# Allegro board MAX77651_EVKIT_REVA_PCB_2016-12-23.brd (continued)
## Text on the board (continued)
FAB_NOTES: NOTES: | FINISH: | TESTING: | MISCELLANEOUS: | TOOLING: | 15.  CHECK ALL THAT APPLY | 16.  VENDOR LOGO & DATE CODE REQUIRED IN INK ON BOTTOM SIDE ONLY. DATE CODE FORMAT MUST BE YYWW ONLY | 17.  FINAL ELECTRICAL TEST TO BE PERFORMED USING PROVIDED IPC-D-356A NETLIST OR ODB++ FORMAT FILE. | 18.  A TIME DOMAIN REFLECTOMETER REPORT FOR EACH IMPEDANCE CONTROLLED LAYER AND A CERTIFICATE | 24.  THIEVING: | 23.  FINISHED SURFACE CONTACTS AND FILLED VIAS TO BE FREE OF ANY PITS. SCRATCHES PROBE MARKS | 19.  FOR BLIND AND BURIED VIA INFORMATION REFER TO DRILL CHART. | 21.  ALL MICRO-VIAS LESS THAN 0.006 INCHES FHS WILL BE PLATED SHUT WITH COPPER, UNLESS OTHERWISE SPECIFIED. | 22.  FOR VIA SIZES XX.XX INCH USE NON CONDUCTIVE VIA FILL AND CAP | 13.  DRILL SIZES ARE FINISHED HOLE SIZES. ALL HOLES SHALL BE LOCATED WITHIN .005 DTP. | 14.  CHECK ALL THAT APPLY | 25.  PEMNUT | 9.  ALL TRACES FILLETED OPTION TO ENHANCE RELIABILITY AT PAD JUNCTIONS | 10.  LAYER TO LAYER REGISTRATIONS SHALL BE WITHIN .003 INCHES. | MATERIAL: | 11.  PLATING SPECIFICATION: | 12.  CHECK ALL THAT APPLY | 8.  IF STATED IN THE LAMINATION DIAGRAM, THE DIELECTRIC THICKNESS OF ANY | 1.  DIMENSIONS ARE IN INCHES (EXCEPT WHERE NOTED). | 3.  THE PCB SHALL BE FABRICATED TO IPC-6012, TYPE X, CLASS 2. | 4.  BOARD MATERIAL & CONSTRUCTION SHALL MEET THE REQUIREMENTS OF UL796 | 5.  OVERALL BOARD THICKNESS REFER TO LAMINATION DIAGRAM. TOLERANCE APPLIES | 6.  BOW & TWIST NOT TO EXCEED 0.0075 IN. (0.75%) PER LINEAR INCH. | 7.  PHOTO ETCH CIRCUITRY PER ENCLOSED GERBER RS274X OR ODB++ FORMAT FILE. | 2.  BOARD MATERIAL: | ( )  APPLY SILKSCREEN TO TOP SIDE USING A NON-CONDUCTIVE, WHITE EPOXY | ( )  OTHER ________________________ | (x)  APPLY SILKSCREEN TO BOTH SIDES USING A NON-CONDUCTIVE, WHITE EPOXY | (x)  GREEN SOLDERMASK OVER BARE COPPER/BARE GOLD (BOTH SIDES) WITH LIQUID PHOTO IMAGEABLE INK (LPI) | ( )  GREEN TAIYO PSR-4000 | ( )  FINGERS TO BE GOLD PLATED. | ( )  FINISH CONDUCTOR SURFACES: IMMERSION GOLD, 2-5 MICRO INCHES OVER | (X)  SUPPLIER MAY ADD THIEVING TO COMPENSATE FOR LOW COPPER DENSITY AREAS ON THIS DESIGN. | ( )  SUPPLIER MAY NOT ADD THIEVING TO COMPENSATE FOR LOW COPPER DENSITY AREAS ON THIS DESIGN. | ( )  NON-CONDUCTIVE EPOXY. FILL AND CAP ALL 0.XXXX INCH DRILLED VIAS. | ( )  SILVER. FILL AND CAP ALL 0.XXXX INCH DRILLED VIAS. | ( )  ELECTODEPOSITED HARD GOLD PLATE, TYPE 1 (99.7% MIN GOLD), GRADE C | (X) LEAD FREE AND RoHS COMPLIANT OR EQUIVALENT LEAD FREE PLATING | (REQUIRED UNLESS OTHERWISE SPECIFIED IN QUOTE) | THE PCB SHALL HAVE A VERIFICATION STAMP. | OF COMPLIANCE SHALL BE PROVIDED BY VENDOR AT TIME OF SHIPMENT. | ( )  PEMNUT TO BE INSTALLED BY SUPPLIER | ( )  PEMNUT NOT TO BE INSTALLED BY SUPPLIER | OR OTHER DEFORMITIES THAT COULD EFFECT THE APPERANCE AND PERFORMACE OF THE CONTACT | SURFACE. CONTACTS ARE TO BE AS FLAT AS POSSIBLE. NOT TO EXCEED +/- 0.001" OF FLATNESS. | (x)  FINISH CONDUCTOR SURFACES: IMMERSION GOLD, 3-8 MICRO INCHES OVER | (X)  STARTING AND FINISH COPPER WEIGHT FOR OUTER LAYERS TO BE (1 OZ). | ( )  STARTING COPPER WEIGHT FOR OUTER LAYERS CAN BE (1 OZ), THE FINISH COPPER WEIGHT IS (2 OZ). | ( )  FILLETED | (X)  NOT FILLETED | ( )  STARTING COPPER WEIGHT FOR OUTER LAYERS TO BE (2 OZ), THE FINISH COPPER WEIGHT IS (2 OZ)MINIMUM. | SO AS TO HINDER PROPER SOLDER WICKING. | (X)  FR4 ( RoHS COMPLIANT) OR EQUIVALENT | ( )  NELCO-4000-13 OR EQUIVALENT | ( )  370HR (RoHS COMPLIANT) OR EQUIVALENT | ( )  ROGERS 4350B | ( )  ROGERS 4003C | MINIMUM BARREL PLATING OF .001 IN. PLATED HOLES SHALL NOT BE ROUGH OR IRREGULAR | ( )  ISOLA-FR408HR | CONTROLLED IMPEDANCE LAYER IS FOR REFERENCE ONLY. FINAL ACCEPTANCE | SHALL BE DETERMINED BY THESE LAYERS HAVING A CHARACTERISTIC | IMPEDANCE OF +/-10% OHMS AS STATED IN THE LAMINATION DIAGRAM. THE | VENDOR CAN MAKE ADJUSTMENTS AS LONG AS THE STATED IMPEDANCE AND | OVERALL BOARD THICKNESS IS MAINTAINED. ANY ADJUSTMENT MADE TO TRACE | WIDTH OR SPACING MUST HAVE PRIOR WRITTEN APPROVAL FROM MAXIM. | WHERE SPACING PERMITS. | LEGEND TO LEGEND +/- 0.007 INCHES | WORKMANSHIP SHALL CONFORM TO IPC-A-600, CLASS 2, CURRENT REVISIONS. | WITH FLAMMABILITY RATING OF 94V-O. | AFTER ALL LAMINATION AND PLATING PROCESSES. IT IS TO BE MEASURED FROM | TOP PCB METAL TO BOTTOM PCB METAL UNLESS OTHERWISE SPECIFIED. | BOW & TWIST SHOULD BE MEASURED PER IPC-TM-650, METHOD 2.4.22. | DRILL LOCATION AND SIZE CONTROLLED BY EXCELLON CNC DRILL FILE. | THE STARTING WEIGHT CAN BE (<2 OZ) AS LONG AS THE FINISH COPPER WEIGHT IS (2 OZ). | UNLESS OTHERWISE SPECIFIED | THE STARTING WEIGHT CAN BE (0.5 OZ) AS LONG AS THE FINISH COPPER WEIGHT IS (2 OZ). | FOR OUTER LAYERS WHERE SPACING PREVENTS THE USE OF (1 OZ) AS A STARTING WEIGHT, | BASED INK PER ARTWORK. | PER ARTWORK. | (KNOOP HARDNESS 130-200), CLASS 1 (50-100 MICRO INCHES THICK) IN ACCORDANCE WITH MIL-G-45204C. | GENERAL SURFACING REQUIREMENTS MUST MEET ANSI/IPC-A-600(CURRENT REV) SECTION 4.0, | CLASS 3 (50-100 MICROINCHES THICK) OVER ELECTRODEPOSITED NICKEL PLATE | IN ACCORDANCE WITH ANSI/IPC-A-600D, SECTION 4.0, CLASS 3 (200-600 MICROINCHES THICK). | 118-236 MICRO INCHES MINIMUM OF ELECTROLESS NICKEL. | 100 MICRO INCHES MINIMUM OF ELECTROLESS NICKEL. | (USE CHECKED ITEMS FOR MATERIAL) | FOR OUTER LAYERS WHERE SPACING PREVENTS THE USE OF (1 OZ) AS A STARTING WEIGHT | THE STARTING WEIGHT CAN BE (0.5 OZ) AS LONG AS THE FINISH COPPER WEIGHT IS (1 OZ) | (USE CHECKED ITEMS FOR PLATING) | (USE CHECKED ITEMS FOR TOOLING) | UNLESS OTHERWISE SPECIFIED: | NOT TO SCALE | TEMPLATE REV 1.7 | TOLERANCES UNLESS OTHERWISE SPECIFIED | +/- | FRACTIONS | SEE NOTES | .XXX +/- .005 | .XX +/- .01 | DECIMALS | ANGLES | THE INFORMATION CONTAINED IN THIS DOCUMENT | IS PROPRIETARY TO MAXIM. THE INFORMATION IN | THIS DOCUMENT IS NOT TO BE SHOWN, REPRODUCED, | OR DISCLOSED TO ANYONE OUTSIDE OF MAXIM | WITHOUT PRIOR WRITTEN PERMISSION FROM MAXIM. | DRAWN BY: | CHECKED BY: | APPR. BY: | LAKSHMI BHUJ | DATE: | 12/20/2016 | SIZE | E | DRAWING NO. | SHEET 1 OF 1 | REV | A | DESCRIPTION | REVISIONS | APPROVED | DATE | TITLE: | RELEASE | MAX77651 EVALUATION BOARD | FABRICATION DWG. | XX-XXXXXX-XX
User.25: FIGURE | SIZE | 8.0 | 12.01 | 32.0 | 35.43 | 37.4 | 39.37 | 41.34 | 45.28 | 62.99 | 70.87 | 125.0 | 41.34x25.59 | 51.18x27.56 | DRILL CHART: TOP to BOTTOM | ALL UNITS ARE IN MILS | TOLERANCE | +3.0/-6.0 | +3.0/-3.0 | PLATED | NON-PLATED | QTY | 365 | 8 | 3 | 6 | 5 | 25 | 4 | 47 | 12 | 2
User.27: FIGURE | SIZE | 8.0 | DRILL CHART: INTERNAL2 to INTERNAL3 | ALL UNITS ARE IN MILS | TOLERANCE | +3.0/-6.0 | PLATED | QTY | 18
User.28: FIGURE | SIZE | 4.0 | DRILL CHART: TOP to INTERNAL2 | ALL UNITS ARE IN MILS | TOLERANCE | +0.0/-4.0 | PLATED | QTY | 86
User.29: FIGURE | SIZE | 8.0 | DRILL CHART: INTERNAL3 to BOTTOM | ALL UNITS ARE IN MILS | TOLERANCE | +3.0/-6.0 | PLATED | QTY | 84
